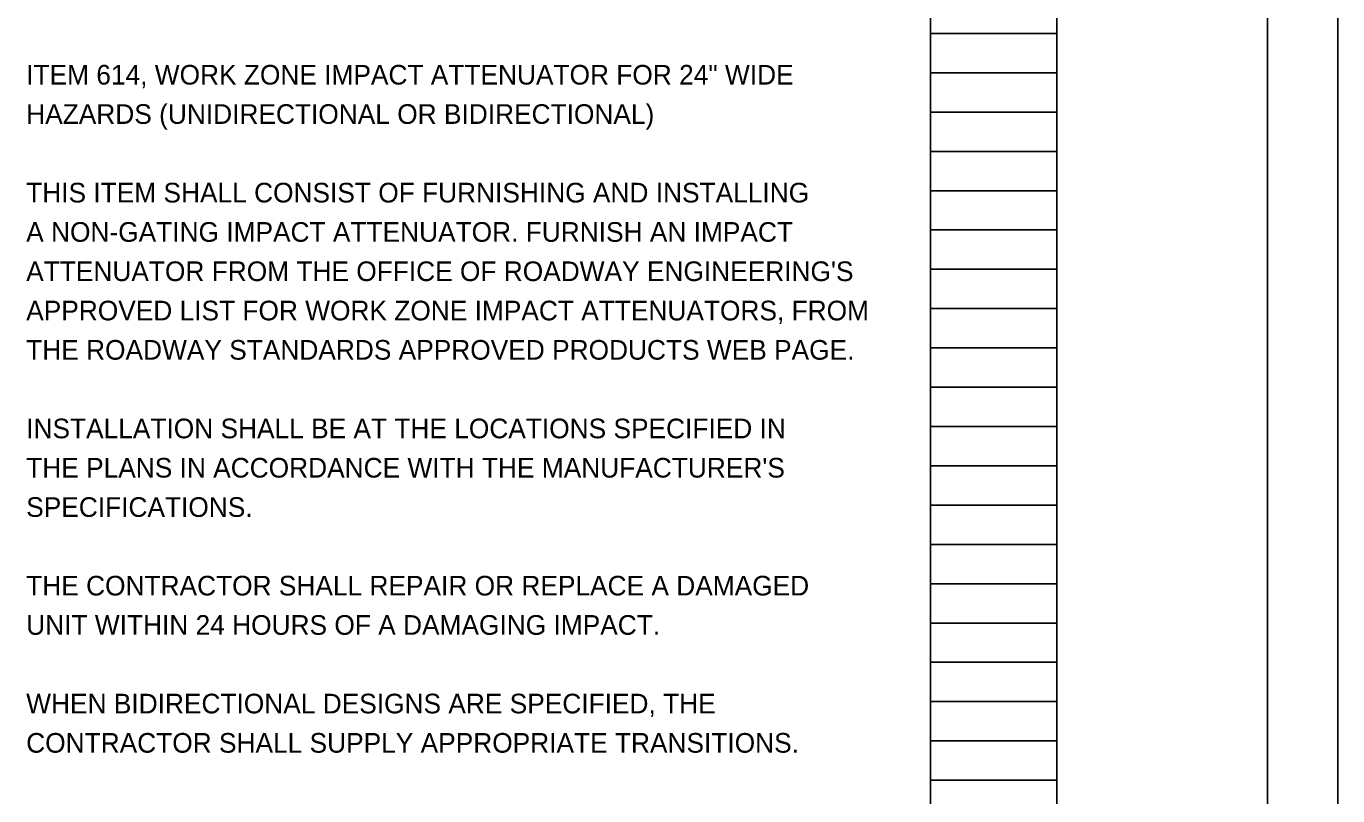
# Model space of a CAD drawing. Extents: x 0 to 34, y 0 to 22.
# Drawn here: x 24.66 to 34, y 5.63 to 11.11 of the extents above; entities that cross this region are included whole.
import ezdxf

# ---------------------------------------------------------------- set-up
doc = ezdxf.new("R2010")
doc.units = 0
for name, color, linetype in [('SH_Border', 7, 'Continuous'), ('SH_Cut_Line', 7, 'Continuous'), ('SH_Data', 7, 'Continuous'), ('SH_Text', 7, 'Continuous')]:
    doc.layers.add(name, color=color, linetype=linetype)

msp = doc.modelspace()

# ---------------------------------------------------------------- linework, layer by layer
at = {"layer": 'SH_Border'}
msp.add_line((32, 0.5), (32, 21.5), dxfattribs=at)
msp.add_lwpolyline([(1.5, 21.5), (33.5, 21.5), (33.5, 0.5), (1.5, 0.5)], close=True, dxfattribs=at)
at = {"layer": 'SH_Cut_Line'}
msp.add_lwpolyline([(0, 0), (34, 0), (34, 22), (0, 22)], close=True, dxfattribs=at)
at = {"layer": 'SH_Data'}
for p, q in [((31.1, 0.98), (31.1, 21.14)), ((32, 0.98), (32, 21.14)), ((31.1, 11.06), (32, 11.06)), ((31.1, 10.78), (32, 10.78)), ((31.1, 10.5), (32, 10.5)), ((31.1, 10.22), (32, 10.22)), ((31.1, 9.94), (32, 9.94)), ((31.1, 9.66), (32, 9.66)), ((31.1, 9.38), (32, 9.38)), ((31.1, 9.1), (32, 9.1)), ((31.1, 8.82), (32, 8.82)), ((31.1, 8.54), (32, 8.54)), ((31.1, 8.26), (32, 8.26)), ((31.1, 7.98), (32, 7.98)), ((31.1, 7.7), (32, 7.7)), ((31.1, 7.42), (32, 7.42)), ((31.1, 7.14), (32, 7.14)), ((31.1, 6.86), (32, 6.86)), ((31.1, 6.58), (32, 6.58)), ((31.1, 6.3), (32, 6.3)), ((31.1, 6.02), (32, 6.02)), ((31.1, 5.74), (32, 5.74))]:
    msp.add_line(p, q, dxfattribs=at)

# ---------------------------------------------------------------- texts
at = {"layer": 'SH_Text'}
for s, p in [('ITEM 614, WORK ZONE IMPACT ATTENUATOR FOR 24" WIDE', (24.66, 10.6961)), ('HAZARDS (UNIDIRECTIONAL OR BIDIRECTIONAL)', (24.66, 10.4161)), ('THIS ITEM SHALL CONSIST OF FURNISHING AND INSTALLING', (24.66, 9.8561)), ('A NON-GATING IMPACT ATTENUATOR. FURNISH AN IMPACT', (24.66, 9.5761)), ("ATTENUATOR FROM THE OFFICE OF ROADWAY ENGINEERING'S", (24.66, 9.2961)), ('APPROVED LIST FOR WORK ZONE IMPACT ATTENUATORS, FROM', (24.66, 9.0161)), ('THE ROADWAY STANDARDS APPROVED PRODUCTS WEB PAGE.', (24.66, 8.7361)), ('INSTALLATION SHALL BE AT THE LOCATIONS SPECIFIED IN', (24.66, 8.1761)), ("THE PLANS IN ACCORDANCE WITH THE MANUFACTURER'S", (24.66, 7.8961)), ('SPECIFICATIONS.', (24.66, 7.6161)), ('THE CONTRACTOR SHALL REPAIR OR REPLACE A DAMAGED', (24.66, 7.0561)), ('UNIT WITHIN 24 HOURS OF A DAMAGING IMPACT.', (24.66, 6.7761)), ('WHEN BIDIRECTIONAL DESIGNS ARE SPECIFIED, THE', (24.66, 6.2161)), ('CONTRACTOR SHALL SUPPLY APPROPRIATE TRANSITIONS.', (24.66, 5.9361))]:
    msp.add_text(s, height=0.14, dxfattribs=at).set_placement(p)

doc.saveas('drawing.dxf')
